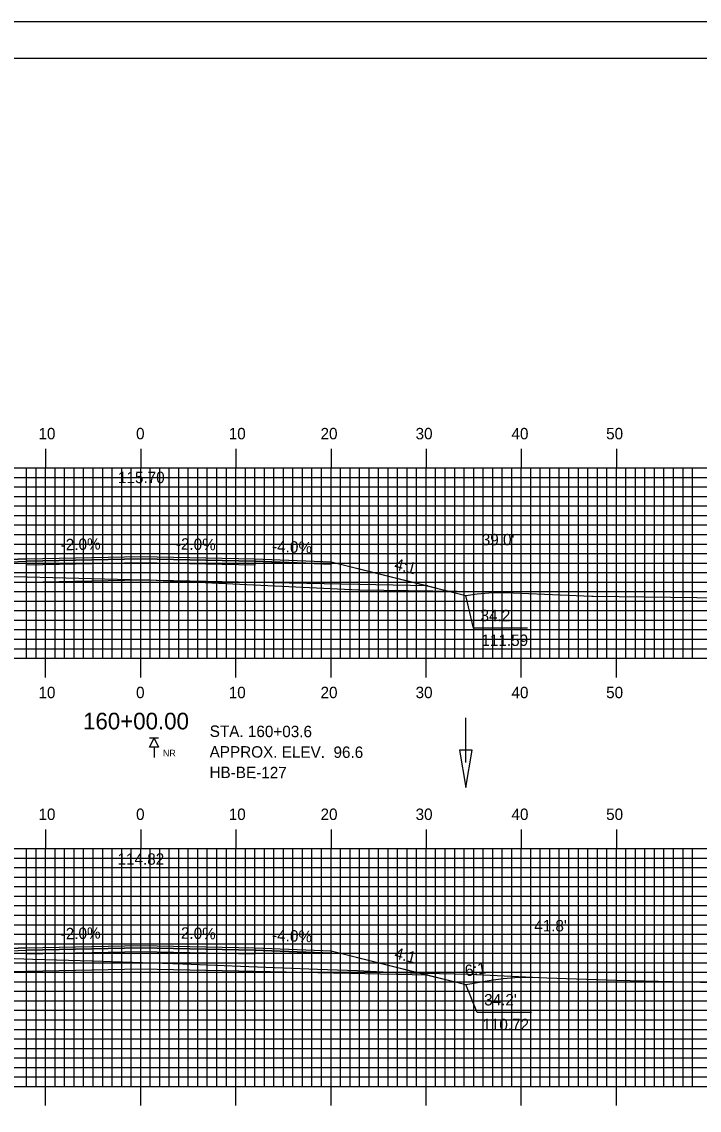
# Model space of a CAD drawing. Extents: x 1779893 to 1780236, y 442591 to 442811.
# Drawn here: x 1780045.9 to 1780117.1, y 442696.2 to 442810.5 of the extents above; entities that cross this region are included whole.
import ezdxf

# ---------------------------------------------------------------- set-up
doc = ezdxf.new("R2010")
doc.units = 0
for name, color, linetype in [('ANNOTATION', 7, 'Continuous'), ('BORDER', 7, 'Continuous'), ('BORING - NO REFUSAL', 7, 'Continuous'), ('D_Drainage_Ditch_Line', 7, 'Continuous'), ('D_Roadway_Centerline', 7, 'Continuous'), ('D_Roadway_Centerline_Text', 7, 'Continuous'), ('D_Roadway_Edge_Shoulder', 7, 'Continuous'), ('D_Roadway_Edge_TW', 7, 'Continuous'), ('D_Roadway_Pavement', 7, 'Continuous'), ('D_Roadway_SlopeLines', 7, 'Continuous'), ('D_Roadway_SubGrade', 7, 'Continuous'), ('D_Text_Standard', 7, 'Continuous'), ('H_V ANNOTATION', 7, 'Continuous'), ('MAJOR', 7, 'Continuous'), ('MINOR', 7, 'Continuous'), ('PLOT BOUNDARY', 7, 'Continuous'), ('S_Roadway_Centerline', 7, 'Continuous')]:
    doc.layers.add(name, color=color, linetype=linetype)

msp = doc.modelspace()

# ---------------------------------------------------------------- linework, layer by layer
at = {"layer": 'ANNOTATION'}
for points in [[(1780099.03, 442746.84), (1780093.34, 442746.84), (1780092.53, 442750.26)], [(1780099.42, 442706.45), (1780093.73, 442706.45), (1780092.53, 442709.38)]]:
    msp.add_lwpolyline(points, dxfattribs=at)
at = {"layer": 'BORDER'}
msp.add_lwpolyline([(1779908.76, 442596.67), (1780228.76, 442596.67), (1780228.76, 442806.67), (1779908.76, 442806.67)], close=True, dxfattribs=at)
at = {"layer": 'BORING - NO REFUSAL'}
for p, q in [((1780060.24, 442735.27), (1780059.28, 442735.27)), ((1780059.76, 442734.31), (1780059.76, 442733.25))]:
    msp.add_line(p, q, dxfattribs=at)
msp.add_lwpolyline([(1780059.76, 442735.27), (1780060.24, 442734.31), (1780059.28, 442734.31)], close=True, dxfattribs=at)
at = {"layer": 'D_Drainage_Ditch_Line'}
msp.add_line((1780092.53, 442732.71), (1780092.53, 442737.41), dxfattribs=at)
msp.add_lwpolyline([(1780093.19, 442734.02), (1780091.87, 442734.02), (1780092.53, 442730.09)], close=True, dxfattribs=at)
at = {"layer": 'D_Roadway_Centerline'}
for points in [[(1780003.83, 442753.25), (1780005.08, 442753.21), (1780006.33, 442753.13), (1780007.58, 442753), (1780008.83, 442752.82), (1780024.18, 442750.26), (1780028.18, 442751.26), (1780038.36, 442753.8), (1780046.36, 442754.12), (1780058.36, 442754.36), (1780070.36, 442754.12), (1780078.36, 442753.8), (1780088.53, 442751.26), (1780092.53, 442750.26), (1780093.73, 442750.43), (1780094.94, 442750.53), (1780096.14, 442750.58), (1780097.34, 442750.56)], [(1779997.87, 442713.47), (1779999.12, 442713.39), (1780000.37, 442713.28), (1780001.62, 442713.12), (1780002.87, 442712.94), (1780024.18, 442709.38), (1780028.18, 442710.38), (1780038.36, 442712.93), (1780046.36, 442713.25), (1780058.36, 442713.49), (1780070.36, 442713.25), (1780078.36, 442712.93), (1780088.53, 442710.38), (1780092.53, 442709.38), (1780095.2, 442709.83), (1780096.45, 442710), (1780097.7, 442710.11), (1780098.95, 442710.16), (1780100.2, 442710.13)]]:
    msp.add_lwpolyline(points, dxfattribs=at)
at = {"layer": 'D_Roadway_Edge_Shoulder'}
for points in [[(1780046.36, 442754.12), (1780038.36, 442753.8), (1780038.36, 442753.55), (1780046.36, 442753.87)], [(1780070.36, 442754.12), (1780078.36, 442753.8), (1780078.36, 442753.55), (1780070.36, 442753.87)], [(1780046.36, 442713.25), (1780038.36, 442712.93), (1780038.36, 442712.68), (1780046.36, 442713)], [(1780070.36, 442713.25), (1780078.36, 442712.93), (1780078.36, 442712.68), (1780070.36, 442713)]]:
    msp.add_lwpolyline(points, close=True, dxfattribs=at)
at = {"layer": 'D_Roadway_Edge_TW'}
for points in [[(1780046.36, 442753.87), (1780046.36, 442754.12), (1780058.36, 442754.36), (1780070.36, 442754.12), (1780070.36, 442753.87), (1780058.36, 442754.11)], [(1780046.36, 442713), (1780046.36, 442713.25), (1780058.36, 442713.49), (1780070.36, 442713.25), (1780070.36, 442713), (1780058.36, 442713.24)]]:
    msp.add_lwpolyline(points, close=True, dxfattribs=at)
at = {"layer": 'D_Roadway_Pavement'}
for points in [[(1780046.36, 442753.46), (1780046.36, 442753.87), (1780058.36, 442754.11), (1780070.36, 442753.87), (1780070.36, 442753.46), (1780058.36, 442753.7)], [(1780046.36, 442712.58), (1780046.36, 442713), (1780058.36, 442713.24), (1780070.36, 442713), (1780070.36, 442712.58), (1780058.36, 442712.82)]]:
    msp.add_lwpolyline(points, close=True, dxfattribs=at)
at = {"layer": 'D_Roadway_SlopeLines'}
for points in [[(1780078.36, 442753.8), (1780092.53, 442750.26)], [(1780092.53, 442750.26), (1780093.73, 442750.43), (1780094.94, 442750.53), (1780096.14, 442750.58), (1780097.34, 442750.56)], [(1780078.36, 442712.93), (1780092.53, 442709.38)], [(1780092.53, 442709.38), (1780095.2, 442709.83), (1780096.45, 442710), (1780097.7, 442710.11), (1780098.95, 442710.16), (1780100.2, 442710.13)]]:
    msp.add_lwpolyline(points, dxfattribs=at)
at = {"layer": 'D_Roadway_SubGrade'}
for points in [[(1780046.36, 442751.62), (1780028.18, 442751.26), (1780038.36, 442753.8), (1780038.36, 442753.55), (1780046.36, 442753.87), (1780058.36, 442754.11), (1780070.36, 442753.87), (1780078.36, 442753.55), (1780078.36, 442753.8), (1780088.53, 442751.26), (1780070.36, 442751.62), (1780058.36, 442751.86)], [(1780046.36, 442710.75), (1780028.18, 442710.38), (1780038.36, 442712.93), (1780038.36, 442712.68), (1780046.36, 442713), (1780058.36, 442713.24), (1780070.36, 442713), (1780078.36, 442712.68), (1780078.36, 442712.93), (1780088.53, 442710.38), (1780070.36, 442710.75), (1780058.36, 442710.99)]]:
    msp.add_lwpolyline(points, close=True, dxfattribs=at)
at = {"layer": 'MAJOR'}
for p, q in [((1780048.36, 442765.67), (1780048.36, 442763.67)), ((1780058.36, 442765.67), (1780058.36, 442763.67)), ((1780068.36, 442765.67), (1780068.36, 442763.67)), ((1780078.36, 442765.67), (1780078.36, 442763.67)), ((1780088.36, 442765.67), (1780088.36, 442763.67)), ((1780098.36, 442765.67), (1780098.36, 442763.67)), ((1780108.36, 442765.67), (1780108.36, 442763.67)), ((1779918.36, 442763.67), (1780198.36, 442763.67)), ((1779918.36, 442763.67), (1780198.36, 442763.67)), ((1780048.36, 442743.67), (1780048.36, 442763.67)), ((1780058.36, 442743.67), (1780058.36, 442763.67)), ((1780068.36, 442743.67), (1780068.36, 442763.67)), ((1780078.36, 442743.67), (1780078.36, 442763.67)), ((1780088.36, 442743.67), (1780088.36, 442763.67)), ((1780098.36, 442743.67), (1780098.36, 442763.67)), ((1780108.36, 442743.67), (1780108.36, 442763.67)), ((1779918.36, 442758.67), (1780198.36, 442758.67)), ((1779918.36, 442753.67), (1780198.36, 442753.67)), ((1779918.36, 442748.67), (1780198.36, 442748.67)), ((1779918.36, 442743.67), (1780198.36, 442743.67)), ((1779918.36, 442743.67), (1780198.36, 442743.67)), ((1780048.36, 442741.66), (1780048.36, 442743.67)), ((1780058.36, 442741.66), (1780058.36, 442743.67)), ((1780068.36, 442741.66), (1780068.36, 442743.67)), ((1780078.36, 442741.66), (1780078.36, 442743.67)), ((1780088.36, 442741.66), (1780088.36, 442743.67)), ((1780098.36, 442741.66), (1780098.36, 442743.67)), ((1780108.36, 442741.66), (1780108.36, 442743.67)), ((1780048.36, 442725.67), (1780048.36, 442723.67)), ((1780058.36, 442725.67), (1780058.36, 442723.67)), ((1780068.36, 442725.67), (1780068.36, 442723.67)), ((1780078.36, 442725.67), (1780078.36, 442723.67)), ((1780088.36, 442725.67), (1780088.36, 442723.67)), ((1780098.36, 442725.67), (1780098.36, 442723.67)), ((1780108.36, 442725.67), (1780108.36, 442723.67)), ((1779918.36, 442723.67), (1780198.36, 442723.67)), ((1779918.36, 442723.67), (1780198.36, 442723.67)), ((1780048.36, 442698.67), (1780048.36, 442723.67)), ((1780058.36, 442698.67), (1780058.36, 442723.67)), ((1780068.36, 442698.67), (1780068.36, 442723.67)), ((1780078.36, 442698.67), (1780078.36, 442723.67)), ((1780088.36, 442698.67), (1780088.36, 442723.67)), ((1780098.36, 442698.67), (1780098.36, 442723.67)), ((1780108.36, 442698.67), (1780108.36, 442723.67)), ((1779918.36, 442718.67), (1780198.36, 442718.67)), ((1779918.36, 442713.67), (1780198.36, 442713.67)), ((1779918.36, 442708.67), (1780198.36, 442708.67)), ((1779918.36, 442703.67), (1780198.36, 442703.67)), ((1779918.36, 442698.67), (1780198.36, 442698.67)), ((1779918.36, 442698.67), (1780198.36, 442698.67)), ((1780048.36, 442696.66), (1780048.36, 442698.67)), ((1780058.36, 442696.66), (1780058.36, 442698.67)), ((1780068.36, 442696.66), (1780068.36, 442698.67)), ((1780078.36, 442696.66), (1780078.36, 442698.67)), ((1780088.36, 442696.66), (1780088.36, 442698.67)), ((1780098.36, 442696.66), (1780098.36, 442698.67)), ((1780108.36, 442696.66), (1780108.36, 442698.67))]:
    msp.add_line(p, q, dxfattribs=at)
at = {"layer": 'MINOR'}
for p, q in [((1780046.36, 442743.67), (1780046.36, 442763.67)), ((1780047.36, 442743.67), (1780047.36, 442763.67)), ((1780049.36, 442743.67), (1780049.36, 442763.67)), ((1780050.36, 442743.67), (1780050.36, 442763.67)), ((1780051.36, 442743.67), (1780051.36, 442763.67)), ((1780052.36, 442743.67), (1780052.36, 442763.67)), ((1780053.36, 442743.67), (1780053.36, 442763.67)), ((1780054.36, 442743.67), (1780054.36, 442763.67)), ((1780055.36, 442743.67), (1780055.36, 442763.67)), ((1780056.36, 442743.67), (1780056.36, 442763.67)), ((1780057.36, 442743.67), (1780057.36, 442763.67)), ((1780059.36, 442743.67), (1780059.36, 442763.67)), ((1780060.36, 442743.67), (1780060.36, 442763.67)), ((1780061.36, 442743.67), (1780061.36, 442763.67)), ((1780062.36, 442743.67), (1780062.36, 442763.67)), ((1780063.36, 442743.67), (1780063.36, 442763.67)), ((1780064.36, 442743.67), (1780064.36, 442763.67)), ((1780065.36, 442743.67), (1780065.36, 442763.67)), ((1780066.36, 442743.67), (1780066.36, 442763.67)), ((1780067.36, 442743.67), (1780067.36, 442763.67)), ((1780069.36, 442743.67), (1780069.36, 442763.67)), ((1780070.36, 442743.67), (1780070.36, 442763.67)), ((1780071.36, 442743.67), (1780071.36, 442763.67)), ((1780072.36, 442743.67), (1780072.36, 442763.67)), ((1780073.36, 442743.67), (1780073.36, 442763.67)), ((1780074.36, 442743.67), (1780074.36, 442763.67)), ((1780075.36, 442743.67), (1780075.36, 442763.67)), ((1780076.36, 442743.67), (1780076.36, 442763.67)), ((1780077.36, 442743.67), (1780077.36, 442763.67)), ((1780079.36, 442743.67), (1780079.36, 442763.67)), ((1780080.36, 442743.67), (1780080.36, 442763.67)), ((1780081.36, 442743.67), (1780081.36, 442763.67)), ((1780082.36, 442743.67), (1780082.36, 442763.67)), ((1780083.36, 442743.67), (1780083.36, 442763.67)), ((1780084.36, 442743.67), (1780084.36, 442763.67)), ((1780085.36, 442743.67), (1780085.36, 442763.67)), ((1780086.36, 442743.67), (1780086.36, 442763.67)), ((1780087.36, 442743.67), (1780087.36, 442763.67)), ((1780089.36, 442743.67), (1780089.36, 442763.67)), ((1780090.36, 442743.67), (1780090.36, 442763.67)), ((1780091.36, 442743.67), (1780091.36, 442763.67)), ((1780092.36, 442743.67), (1780092.36, 442763.67)), ((1780093.36, 442743.67), (1780093.36, 442763.67)), ((1780094.36, 442743.67), (1780094.36, 442763.67)), ((1780095.36, 442743.67), (1780095.36, 442763.67)), ((1780096.36, 442743.67), (1780096.36, 442763.67)), ((1780097.36, 442743.67), (1780097.36, 442763.67)), ((1780099.36, 442743.67), (1780099.36, 442763.67)), ((1780100.36, 442743.67), (1780100.36, 442763.67)), ((1780101.36, 442743.67), (1780101.36, 442763.67)), ((1780102.36, 442743.67), (1780102.36, 442763.67)), ((1780103.36, 442743.67), (1780103.36, 442763.67)), ((1780104.36, 442743.67), (1780104.36, 442763.67)), ((1780105.36, 442743.67), (1780105.36, 442763.67)), ((1780106.36, 442743.67), (1780106.36, 442763.67)), ((1780107.36, 442743.67), (1780107.36, 442763.67)), ((1780109.36, 442743.67), (1780109.36, 442763.67)), ((1780110.36, 442743.67), (1780110.36, 442763.67)), ((1780111.36, 442743.67), (1780111.36, 442763.67)), ((1780112.36, 442743.67), (1780112.36, 442763.67)), ((1780113.36, 442743.67), (1780113.36, 442763.67)), ((1780114.36, 442743.67), (1780114.36, 442763.67)), ((1780115.36, 442743.67), (1780115.36, 442763.67)), ((1780116.36, 442743.67), (1780116.36, 442763.67)), ((1779918.36, 442762.67), (1780198.36, 442762.67)), ((1779918.36, 442761.67), (1780198.36, 442761.67)), ((1779918.36, 442760.67), (1780198.36, 442760.67)), ((1779918.36, 442759.67), (1780198.36, 442759.67)), ((1779918.36, 442757.67), (1780198.36, 442757.67)), ((1779918.36, 442756.67), (1780198.36, 442756.67)), ((1779918.36, 442755.67), (1780198.36, 442755.67)), ((1779918.36, 442754.67), (1780198.36, 442754.67)), ((1779918.36, 442752.67), (1780198.36, 442752.67)), ((1779918.36, 442751.67), (1780198.36, 442751.67)), ((1779918.36, 442750.67), (1780198.36, 442750.67)), ((1779918.36, 442749.67), (1780198.36, 442749.67)), ((1779918.36, 442747.67), (1780198.36, 442747.67)), ((1779918.36, 442746.67), (1780198.36, 442746.67)), ((1779918.36, 442745.67), (1780198.36, 442745.67)), ((1779918.36, 442744.67), (1780198.36, 442744.67)), ((1780046.36, 442698.67), (1780046.36, 442723.67)), ((1780047.36, 442698.67), (1780047.36, 442723.67)), ((1780049.36, 442698.67), (1780049.36, 442723.67)), ((1780050.36, 442698.67), (1780050.36, 442723.67)), ((1780051.36, 442698.67), (1780051.36, 442723.67)), ((1780052.36, 442698.67), (1780052.36, 442723.67)), ((1780053.36, 442698.67), (1780053.36, 442723.67)), ((1780054.36, 442698.67), (1780054.36, 442723.67)), ((1780055.36, 442698.67), (1780055.36, 442723.67)), ((1780056.36, 442698.67), (1780056.36, 442723.67)), ((1780057.36, 442698.67), (1780057.36, 442723.67)), ((1780059.36, 442698.67), (1780059.36, 442723.67)), ((1780060.36, 442698.67), (1780060.36, 442723.67)), ((1780061.36, 442698.67), (1780061.36, 442723.67)), ((1780062.36, 442698.67), (1780062.36, 442723.67)), ((1780063.36, 442698.67), (1780063.36, 442723.67)), ((1780064.36, 442698.67), (1780064.36, 442723.67)), ((1780065.36, 442698.67), (1780065.36, 442723.67)), ((1780066.36, 442698.67), (1780066.36, 442723.67)), ((1780067.36, 442698.67), (1780067.36, 442723.67)), ((1780069.36, 442698.67), (1780069.36, 442723.67)), ((1780070.36, 442698.67), (1780070.36, 442723.67)), ((1780071.36, 442698.67), (1780071.36, 442723.67)), ((1780072.36, 442698.67), (1780072.36, 442723.67)), ((1780073.36, 442698.67), (1780073.36, 442723.67)), ((1780074.36, 442698.67), (1780074.36, 442723.67)), ((1780075.36, 442698.67), (1780075.36, 442723.67)), ((1780076.36, 442698.67), (1780076.36, 442723.67)), ((1780077.36, 442698.67), (1780077.36, 442723.67)), ((1780079.36, 442698.67), (1780079.36, 442723.67)), ((1780080.36, 442698.67), (1780080.36, 442723.67)), ((1780081.36, 442698.67), (1780081.36, 442723.67)), ((1780082.36, 442698.67), (1780082.36, 442723.67)), ((1780083.36, 442698.67), (1780083.36, 442723.67)), ((1780084.36, 442698.67), (1780084.36, 442723.67)), ((1780085.36, 442698.67), (1780085.36, 442723.67)), ((1780086.36, 442698.67), (1780086.36, 442723.67)), ((1780087.36, 442698.67), (1780087.36, 442723.67)), ((1780089.36, 442698.67), (1780089.36, 442723.67)), ((1780090.36, 442698.67), (1780090.36, 442723.67)), ((1780091.36, 442698.67), (1780091.36, 442723.67)), ((1780092.36, 442698.67), (1780092.36, 442723.67)), ((1780093.36, 442698.67), (1780093.36, 442723.67)), ((1780094.36, 442698.67), (1780094.36, 442723.67)), ((1780095.36, 442698.67), (1780095.36, 442723.67)), ((1780096.36, 442698.67), (1780096.36, 442723.67)), ((1780097.36, 442698.67), (1780097.36, 442723.67)), ((1780099.36, 442698.67), (1780099.36, 442723.67)), ((1780100.36, 442698.67), (1780100.36, 442723.67)), ((1780101.36, 442698.67), (1780101.36, 442723.67)), ((1780102.36, 442698.67), (1780102.36, 442723.67)), ((1780103.36, 442698.67), (1780103.36, 442723.67)), ((1780104.36, 442698.67), (1780104.36, 442723.67)), ((1780105.36, 442698.67), (1780105.36, 442723.67)), ((1780106.36, 442698.67), (1780106.36, 442723.67)), ((1780107.36, 442698.67), (1780107.36, 442723.67)), ((1780109.36, 442698.67), (1780109.36, 442723.67)), ((1780110.36, 442698.67), (1780110.36, 442723.67)), ((1780111.36, 442698.67), (1780111.36, 442723.67)), ((1780112.36, 442698.67), (1780112.36, 442723.67)), ((1780113.36, 442698.67), (1780113.36, 442723.67)), ((1780114.36, 442698.67), (1780114.36, 442723.67)), ((1780115.36, 442698.67), (1780115.36, 442723.67)), ((1780116.36, 442698.67), (1780116.36, 442723.67)), ((1779918.36, 442722.67), (1780198.36, 442722.67)), ((1779918.36, 442721.67), (1780198.36, 442721.67)), ((1779918.36, 442720.67), (1780198.36, 442720.67)), ((1779918.36, 442719.67), (1780198.36, 442719.67)), ((1779918.36, 442717.67), (1780198.36, 442717.67)), ((1779918.36, 442716.67), (1780198.36, 442716.67)), ((1779918.36, 442715.67), (1780198.36, 442715.67)), ((1779918.36, 442714.67), (1780198.36, 442714.67)), ((1779918.36, 442712.67), (1780198.36, 442712.67)), ((1779918.36, 442711.67), (1780198.36, 442711.67)), ((1779918.36, 442710.67), (1780198.36, 442710.67)), ((1779918.36, 442709.67), (1780198.36, 442709.67)), ((1779918.36, 442707.67), (1780198.36, 442707.67)), ((1779918.36, 442706.67), (1780198.36, 442706.67)), ((1779918.36, 442705.67), (1780198.36, 442705.67)), ((1779918.36, 442704.67), (1780198.36, 442704.67)), ((1779918.36, 442702.67), (1780198.36, 442702.67)), ((1779918.36, 442701.67), (1780198.36, 442701.67)), ((1779918.36, 442700.67), (1780198.36, 442700.67)), ((1779918.36, 442699.67), (1780198.36, 442699.67))]:
    msp.add_line(p, q, dxfattribs=at)
at = {"layer": 'PLOT BOUNDARY'}
msp.add_lwpolyline([(1779892.57, 442590.55), (1780232.57, 442590.55), (1780232.57, 442810.55), (1779892.57, 442810.55)], close=True, dxfattribs=at)
at = {"layer": 'S_Roadway_Centerline'}
for points in [[(1779978.36, 442754.4), (1779987.69, 442753.59), (1779992.67, 442753.3), (1780011.12, 442753.21), (1780013.23, 442753.13), (1780015.36, 442753), (1780025.08, 442752.55), (1780036.36, 442752.49), (1780036.9, 442752.48), (1780058.61, 442751.92), (1780059.28, 442751.91), (1780059.98, 442751.86), (1780081.24, 442750.87), (1780081.37, 442750.86), (1780094.18, 442750.69), (1780105.77, 442750.19), (1780105.91, 442750.19), (1780116.83, 442750.05), (1780128.02, 442749.91)], [(1779982.49, 442714.17), (1779988.63, 442713.86), (1779995.07, 442713.6), (1780000.76, 442713.33), (1780007.19, 442713.15), (1780012.06, 442713.11), (1780016.48, 442712.94), (1780029.01, 442712.66), (1780041.25, 442712.26), (1780047.02, 442712.04), (1780053.26, 442711.88), (1780062.8, 442711.56), (1780069.73, 442711.28), (1780076.94, 442710.98), (1780081.15, 442710.87), (1780085.17, 442710.66), (1780092.85, 442710.47), (1780101.05, 442710.09), (1780108.34, 442709.83), (1780126.08, 442709.42)]]:
    msp.add_lwpolyline(points, dxfattribs=at)

# ---------------------------------------------------------------- texts
at = {"layer": 'ANNOTATION'}
for s, rotation, p in [('-2.0%', 1.1458, (1780049.96, 442755)), ('-2.0%', 358.8542, (1780062.04, 442755.09)), ('-4.0%', 357.7094, (1780072.15, 442754.85)), ('4:1', 345.9638, (1780084.95, 442753.02)), ('-2.0%', 1.1458, (1780049.96, 442714.12)), ('-2.0%', 358.8542, (1780062.04, 442714.21)), ('-4.0%', 357.7094, (1780072.15, 442713.98)), ('4:1', 345.9638, (1780084.95, 442712.14)), ('6:1', 9.4625, (1780092.54, 442710.21))]:
    msp.add_text(s, height=1.2, rotation=rotation, dxfattribs=at).set_placement(p)
for s, p in [("34.2'", (1780094.08, 442747.56)), ('111.59', (1780094.17, 442744.96)), ("34.2'", (1780094.46, 442707.18)), ('110.72', (1780094.27, 442704.58))]:
    msp.add_text(s, height=1.2, dxfattribs=at).set_placement(p)
at = {"layer": 'BORING - NO REFUSAL'}
for s, p in [('STA. 160+03.6', (1780065.61, 442735.4)), ('APPROX. ELEV.  96.6', (1780065.6, 442733.24)), ('HB-BE-127', (1780065.59, 442731.08))]:
    msp.add_text(s, height=1.2, rotation=359.8142, dxfattribs=at).set_placement(p)
msp.add_text('NR', height=0.7, dxfattribs=at).set_placement((1780060.69, 442733.35))
at = {"layer": 'D_Roadway_Centerline'}
for s, p in [('C', (1780058.35, 442754.36)), ('L', (1780058.36, 442754.36)), ('C', (1780058.35, 442713.49)), ('L', (1780058.36, 442713.48))]:
    msp.add_text(s, height=0.0146, dxfattribs=at).set_placement(p)
at = {"layer": 'D_Roadway_Centerline_Text'}
for s, p in [('115.70', (1780055.97, 442762.07)), ('114.82', (1780055.92, 442721.97))]:
    msp.add_text(s, height=1.2, dxfattribs=at).set_placement(p)
at = {"layer": 'D_Text_Standard'}
for s, p in [("39.0'", (1780094.21, 442755.53)), ("41.8'", (1780099.72, 442714.96))]:
    msp.add_text(s, height=1.2, dxfattribs=at).set_placement(p)
at = {"layer": 'H_V ANNOTATION'}
for s, height, p in [('10', 1.2, (1780047.61, 442766.67)), ('0', 1.2, (1780057.87, 442766.67)), ('10', 1.2, (1780067.61, 442766.67)), ('20', 1.2, (1780077.26, 442766.67)), ('30', 1.2, (1780087.25, 442766.67)), ('40', 1.2, (1780097.33, 442766.67)), ('50', 1.2, (1780107.28, 442766.67)), ('10', 1.2, (1780047.61, 442739.47)), ('0', 1.2, (1780057.87, 442739.47)), ('10', 1.2, (1780067.61, 442739.47)), ('20', 1.2, (1780077.26, 442739.47)), ('30', 1.2, (1780087.25, 442739.47)), ('40', 1.2, (1780097.33, 442739.47)), ('50', 1.2, (1780107.28, 442739.47)), ('160+00.00', 1.75, (1780052.3, 442736.19)), ('10', 1.2, (1780047.61, 442726.67)), ('0', 1.2, (1780057.87, 442726.67)), ('10', 1.2, (1780067.61, 442726.67)), ('20', 1.2, (1780077.26, 442726.67)), ('30', 1.2, (1780087.25, 442726.67)), ('40', 1.2, (1780097.33, 442726.67)), ('50', 1.2, (1780107.28, 442726.67))]:
    msp.add_text(s, height=height, dxfattribs=at).set_placement(p)

doc.saveas('drawing.dxf')
